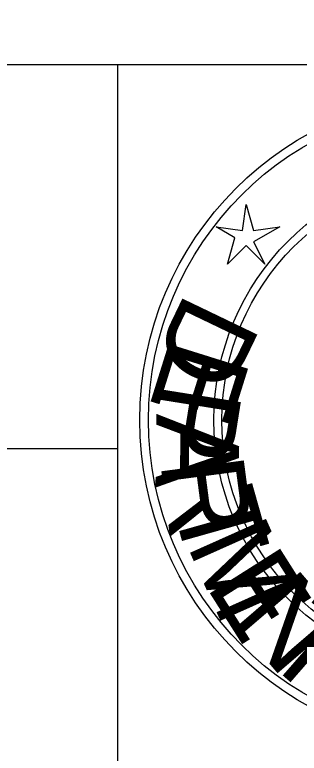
# Model space of a CAD drawing. Extents: x 515543 to 517243, y 660510 to 662861.
# Drawn here: x 516438.4 to 516458.4, y 660536.9 to 660588.8 of the extents above; entities that cross this region are included whole.
import ezdxf

# ---------------------------------------------------------------- set-up
doc = ezdxf.new("R2010")
doc.units = 0
for name, color, linetype in [('great seal', 7, 'Continuous'), ('SHT-BDR', 7, 'Continuous'), ('SHT-BNDRY', 7, 'Continuous')]:
    doc.layers.add(name, color=color, linetype=linetype)

msp = doc.modelspace()

# ---------------------------------------------------------------- linework, layer by layer
at = {"layer": 'great seal'}
msp.add_lwpolyline([(516454.663, 660575.454), (516455.188, 660573.615), (516457.028, 660573.877), (516455.188, 660572.826), (516455.977, 660571.25), (516454.663, 660572.564), (516453.349, 660571.25), (516453.875, 660573.089), (516452.561, 660573.877), (516454.4, 660573.615)], close=True, dxfattribs=at)
msp.add_lwpolyline([(516454.663, 660575.454), (516455.188, 660573.615), (516457.028, 660573.877), (516455.188, 660572.826), (516455.977, 660571.25), (516454.663, 660572.564), (516453.349, 660571.25), (516453.875, 660573.089), (516452.561, 660573.877), (516454.4, 660573.615)], close=True, dxfattribs=at)
msp.add_lwpolyline([(516454.663, 660575.454), (516455.188, 660573.615), (516457.028, 660573.877), (516455.188, 660572.826), (516455.977, 660571.25), (516454.663, 660572.564), (516453.349, 660571.25), (516453.875, 660573.089), (516452.561, 660573.877), (516454.4, 660573.615)], close=True, dxfattribs=at)
for radius in [22.994, 22.994, 22.994, 22.389, 22.389, 22.389, 17.779, 17.779, 17.779, 17.222, 17.222, 17.222]:
    msp.add_circle((516470.184, 660560.292), radius, dxfattribs=at)
at = {"layer": 'SHT-BDR'}
msp.add_lwpolyline([(515667.498, 660585.298), (517167.501, 660585.298), (517167.501, 661535.3), (515667.498, 661535.3)], close=True, dxfattribs=at)
at = {"layer": 'SHT-BNDRY'}
for p, q in [((516445.637, 660535.248), (516445.637, 660585.298)), ((515667.498, 660558.298), (516445.637, 660558.298))]:
    msp.add_line(p, q, dxfattribs=at)

# ---------------------------------------------------------------- texts
at = {"layer": 'great seal'}
for s, rotation, p in [('D', 244.3352, (516450.459, 660569.411)), ('D', 244.3352, (516450.459, 660569.411)), ('D', 244.3352, (516450.459, 660569.411)), ('E', 252.6236, (516449.408, 660566.257)), ('E', 252.6236, (516449.408, 660566.257)), ('E', 252.6236, (516449.408, 660566.257)), ('P', 260.912, (516448.619, 660563.104)), ('P', 260.912, (516448.619, 660563.104)), ('P', 260.912, (516448.619, 660563.104)), ('A', 269.2004, (516448.357, 660560.739)), ('A', 269.2004, (516448.357, 660560.739)), ('A', 269.2004, (516448.357, 660560.739)), ('R', 277.4888, (516448.619, 660557.323)), ('R', 277.4888, (516448.619, 660557.323)), ('R', 277.4888, (516448.619, 660557.323)), ('T', 285.7771, (516449.408, 660554.433)), ('T', 285.7771, (516449.408, 660554.433)), ('T', 285.7771, (516449.408, 660554.433)), ('M', 294.0655, (516450.459, 660551.543)), ('M', 294.0655, (516450.459, 660551.543)), ('M', 294.0655, (516450.459, 660551.543)), ('E', 302.3539, (516451.772, 660548.652)), ('E', 302.3539, (516451.772, 660548.652)), ('E', 302.3539, (516451.772, 660548.652)), ('N', 310.6423, (516453.612, 660546.287)), ('N', 310.6423, (516453.612, 660546.287)), ('N', 310.6423, (516453.612, 660546.287)), ('T', 318.9307, (516455.714, 660543.66)), ('T', 318.9307, (516455.714, 660543.66)), ('T', 318.9307, (516455.714, 660543.66))]:
    msp.add_text(s, height=5.851, rotation=rotation, dxfattribs=at).set_placement(p)

doc.saveas('drawing.dxf')
